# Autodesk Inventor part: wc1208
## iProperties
Shininess: 64.0
Length Units: 11272
Angle Units: 11279
Time Units: 11290
Mass Units: 11286
Length Display Precision: 3
Angle Display Precision: 2
Compacted: True
Part Number: wc1208
Document SubType Name: Modeling
Created: 2004-08
Designer: John Blackburn
Manufacturer: Standard
Standards Organization: Custom
Density: 0.0
Volumn: 0.0
Area: 0.0
PropertySet Name: Model Information
Control State: 0
Master: False
Checked Out: False
Author: John Blackburn
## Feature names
1. Base1
